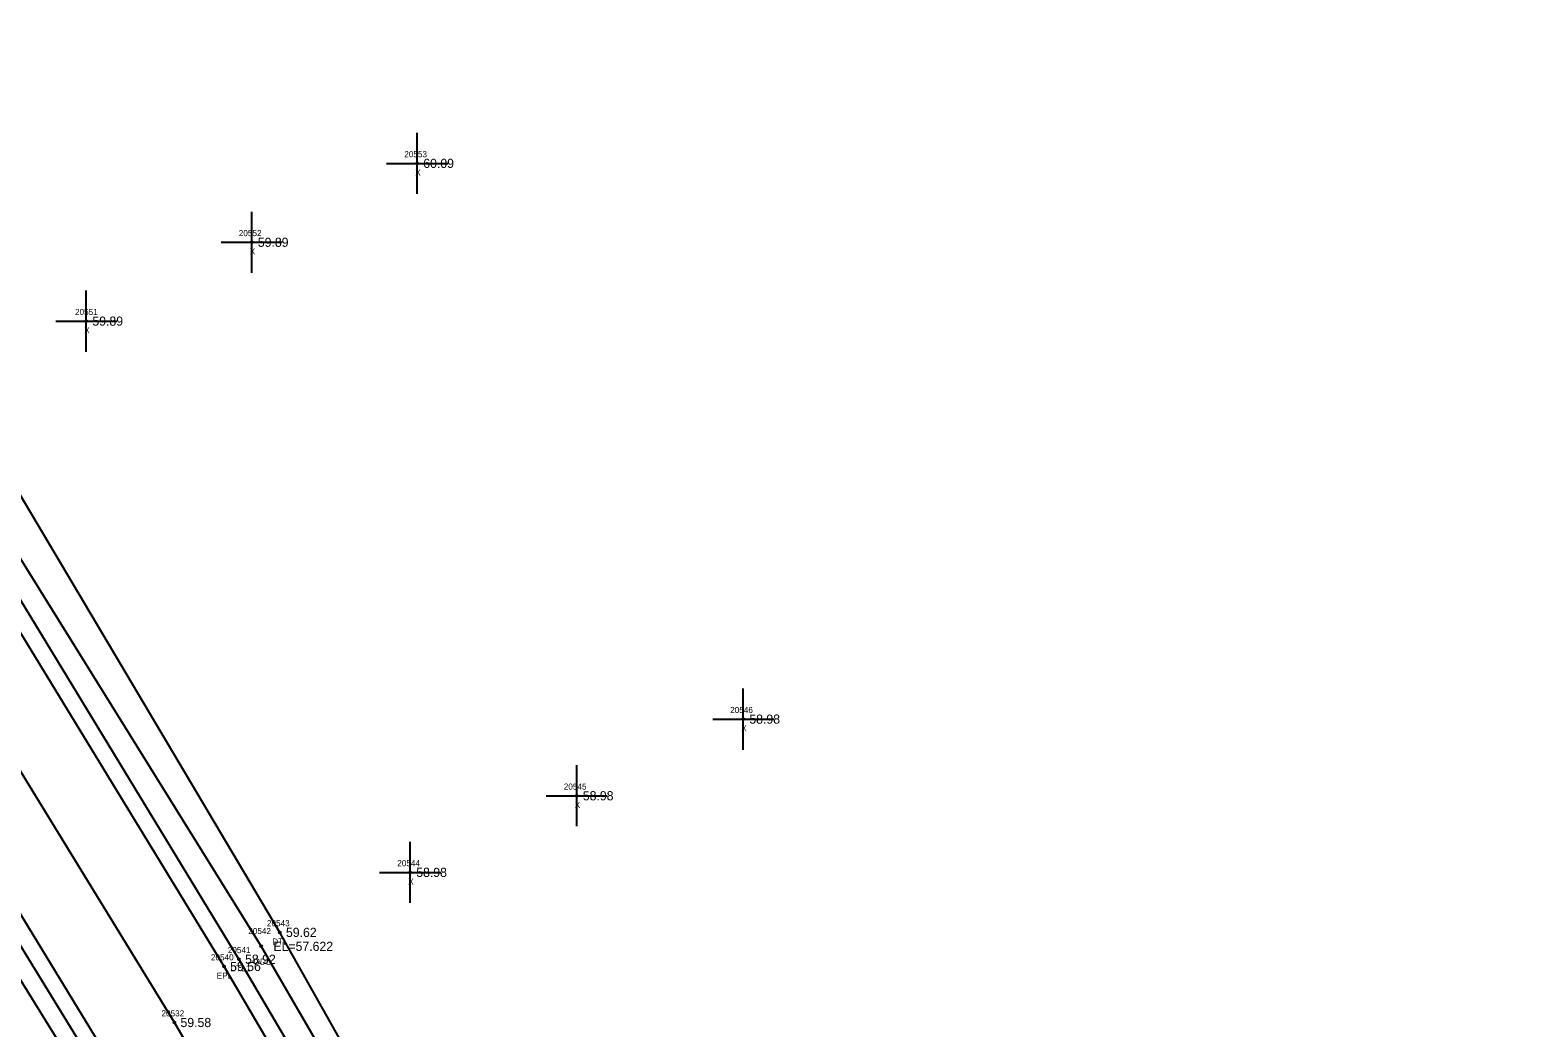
# Model space of a CAD drawing. Extents: x 2396547 to 2397655, y 770185 to 772649.
# Drawn here: x 2397339.4 to 2397586.1, y 770719.1 to 770882.4 of the extents above; entities that cross this region are included whole.
import ezdxf

# ---------------------------------------------------------------- set-up
doc = ezdxf.new("R2010")
doc.units = 0
for name, color, linetype in [('RD_DTM_BkLn1', 7, 'Continuous'), ('RD_EX_H2O', 7, 'Continuous'), ('RD_EX_H2O_txCode', 7, 'Continuous'), ('RD_EX_Misc', 7, 'Continuous'), ('RD_EX_Misc_txCode', 7, 'Continuous'), ('RD_EX_Road', 7, 'Continuous'), ('RD_EX_Road_txCode', 7, 'Continuous'), ('RD_EX_TX_H2O_ELEV', 7, 'Continuous'), ('RD_EX_TX_Misc_ELEV', 7, 'Continuous'), ('RD_EX_TX_Road_ELEV', 7, 'Continuous'), ('RD_HC_Survey_ELEV', 7, 'Continuous'), ('RD_HC_Survey_txCode', 7, 'Continuous'), ('RD_SMD_Locator', 7, 'Continuous')]:
    doc.layers.add(name, color=color, linetype=linetype)

msp = doc.modelspace()

# ---------------------------------------------------------------- linework, layer by layer
at = {"layer": 'RD_DTM_BkLn1'}
msp.add_lwpolyline([(2397565.46, 770206.19), (2397547.69, 770280.33), (2397528.11, 770352.94), (2397504.84, 770424.66), (2397476.69, 770499.34), (2397447.19, 770566.69), (2397412.23, 770635.13), (2397363.03, 770719.95), (2397270.14, 770871.5)], dxfattribs=at)
at = {"layer": 'RD_EX_H2O'}
for points in [[(2397586.15, 770211.51), (2397567.31, 770287.61), (2397548.79, 770357.79), (2397525.19, 770434.22), (2397495.53, 770510.39), (2397465.51, 770576.5), (2397430.55, 770645.5), (2397380.29, 770734.7), (2397327.01, 770824.44), (2397291.42, 770882.36)], [(2397579.43, 770209.93), (2397561.1, 770285.3), (2397543.19, 770356.19), (2397518.98, 770431.67), (2397489.88, 770507.8), (2397460.56, 770573.86), (2397425.02, 770642.83), (2397373.6, 770730.3), (2397319.08, 770819.92), (2397284.14, 770878.8)], [(2397583.73, 770210.91), (2397565.2, 770287.05), (2397546.34, 770357.13), (2397522.25, 770433.23), (2397493.26, 770509.76), (2397463.19, 770575.43), (2397428.34, 770644.33), (2397377.24, 770732.42), (2397321.77, 770821.7), (2397287.01, 770879.96)], [(2397428.38, 770563.87), (2397397.36, 770626.2), (2397348.29, 770710.09), (2397290.43, 770803.51), (2397255.11, 770861.71)], [(2397432.83, 770561.85), (2397399.16, 770627.27), (2397350.75, 770711.42), (2397293.36, 770805.09), (2397257.48, 770863.23)]]:
    msp.add_lwpolyline(points, dxfattribs=at)
at = {"layer": 'RD_EX_Misc'}
for p, q in [((2397402.76, 770855.56), (2397402.76, 770865.56)), ((2397397.76, 770860.56), (2397407.76, 770860.56)), ((2397375.69, 770842.65), (2397375.69, 770852.65)), ((2397370.69, 770847.65), (2397380.69, 770847.65)), ((2397348.61, 770829.74), (2397348.61, 770839.74)), ((2397343.61, 770834.74), (2397353.61, 770834.74)), ((2397456.12, 770764.6), (2397456.12, 770774.6)), ((2397451.12, 770769.6), (2397461.12, 770769.6)), ((2397428.87, 770752.06), (2397428.87, 770762.06)), ((2397423.87, 770757.06), (2397433.87, 770757.06)), ((2397401.61, 770739.52), (2397401.61, 770749.52)), ((2397396.61, 770744.52), (2397406.61, 770744.52))]:
    msp.add_line(p, q, dxfattribs=at)
at = {"layer": 'RD_EX_Road'}
for points in [[(2397576.88, 770209.21), (2397558.85, 770284.47), (2397539.93, 770354.87), (2397515.81, 770430.13), (2397486.97, 770506.75), (2397457.82, 770572.7), (2397422.37, 770641.75), (2397371.16, 770729.12), (2397316.57, 770818.52), (2397280.76, 770876.73)], [(2397553.19, 770205.48), (2397535.12, 770280.96), (2397517, 770349.24), (2397493.4, 770422.78), (2397467.13, 770492.9), (2397441.16, 770551.74), (2397436.66, 770561.67), (2397402.21, 770629.28), (2397353, 770712.83), (2397296, 770806.32), (2397260.16, 770864.73)]]:
    msp.add_lwpolyline(points, dxfattribs=at)
at = {"layer": 'RD_SMD_Locator'}
for centre in [(2397402.76, 770860.56), (2397375.69, 770847.65), (2397348.61, 770834.74), (2397456.12, 770769.6), (2397428.87, 770757.06), (2397401.61, 770744.52), (2397380.29, 770734.7), (2397373.6, 770730.3), (2397377.24, 770732.42), (2397371.16, 770729.12), (2397363.03, 770719.95)]:
    msp.add_circle(centre, 0.15, dxfattribs=at)

# ---------------------------------------------------------------- texts
at = {"layer": 'RD_EX_H2O_txCode'}
for s, p in [('20542', (2397375.12, 770734.42)), ('20543', (2397378.18, 770735.7)), ('DTL', (2397379.05, 770732.7)), ('20541', (2397371.77, 770731.3)), ('ODL', (2397375.99, 770729.42)), ('DTL1', (2397372.19, 770728.3))]:
    msp.add_text(s, height=1, dxfattribs=at).set_placement(p)
at = {"layer": 'RD_EX_Misc_txCode'}
for s, p in [('20553', (2397400.65, 770861.56)), ('X', (2397402.45, 770858.56)), ('20552', (2397373.57, 770848.65)), ('X', (2397375.37, 770845.65)), ('20551', (2397346.77, 770835.74)), ('X', (2397348.29, 770832.74)), ('20546', (2397453.98, 770770.6)), ('X', (2397455.8, 770767.6)), ('20545', (2397426.75, 770758.06)), ('X', (2397428.55, 770755.06)), ('20544', (2397399.5, 770745.52)), ('X', (2397401.3, 770742.52))]:
    msp.add_text(s, height=1, dxfattribs=at).set_placement(p)
at = {"layer": 'RD_EX_Road_txCode'}
for s, p in [('20540', (2397369.01, 770730.12)), ('EPL', (2397369.96, 770727.12))]:
    msp.add_text(s, height=1, dxfattribs=at).set_placement(p)
at = {"layer": 'RD_EX_TX_H2O_ELEV'}
for s, p in [('59.62', (2397381.29, 770733.95)), ('EL=57.622', (2397379.24, 770731.67)), ('58.92', (2397374.6, 770729.55))]:
    msp.add_text(s, height=1.5, dxfattribs=at).set_placement(p)
at = {"layer": 'RD_EX_TX_Misc_ELEV'}
for s, p in [('60.09', (2397403.76, 770859.81)), ('59.89', (2397376.69, 770846.9)), ('59.89', (2397349.61, 770833.99)), ('58.98', (2397457.12, 770768.85)), ('58.98', (2397429.87, 770756.31)), ('58.98', (2397402.61, 770743.77))]:
    msp.add_text(s, height=1.5, dxfattribs=at).set_placement(p)
at = {"layer": 'RD_EX_TX_Road_ELEV'}
msp.add_text('59.56', height=1.5, dxfattribs=at).set_placement((2397372.16, 770728.37))
at = {"layer": 'RD_HC_Survey_ELEV'}
msp.add_text('59.58', height=1.5, dxfattribs=at).set_placement((2397364.03, 770719.2))
at = {"layer": 'RD_HC_Survey_txCode'}
msp.add_text('20532', height=1, dxfattribs=at).set_placement((2397360.92, 770720.95))

doc.saveas('drawing.dxf')
